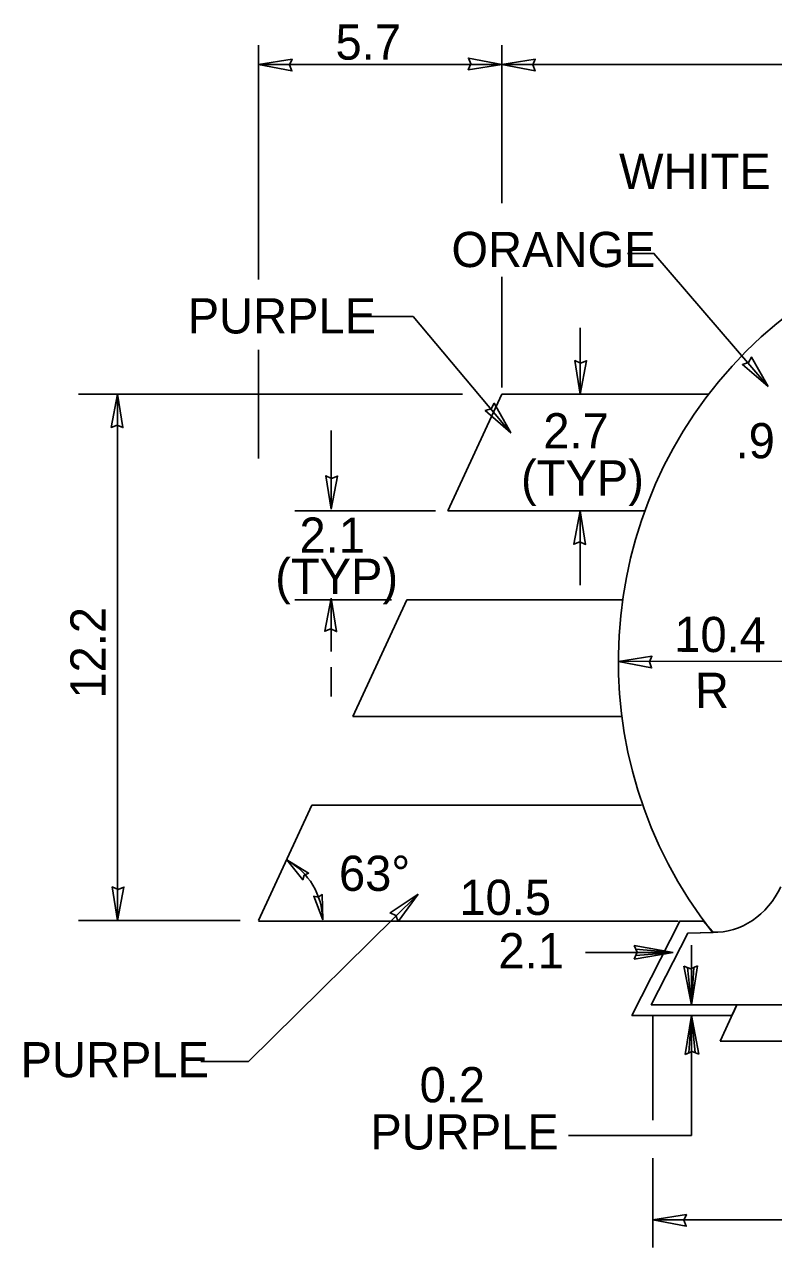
# Model space of a CAD drawing. Extents: x 10268197 to 10268826, y 2141503 to 2142677.
# Drawn here: x 10268493.92 to 10268506.08, y 2142339.57 to 2142359.44 of the extents above; entities that cross this region are included whole.
import ezdxf

# ---------------------------------------------------------------- set-up
doc = ezdxf.new("R2010")
doc.units = 0
doc.layers.add('Default', color=7, linetype='Continuous')

msp = doc.modelspace()

# ---------------------------------------------------------------- linework, layer by layer
at = {"layer": 'Default'}
for p, q in [((10268497.721, 2142355.296), (10268497.721, 2142359.103)), ((10268501.67, 2142356.534), (10268501.67, 2142359.103)), ((10268497.721, 2142358.79), (10268501.67, 2142358.79)), ((10268501.67, 2142358.79), (10268542.432, 2142358.79)), ((10268501.67, 2142353.544), (10268501.67, 2142355.338)), ((10268502.944, 2142354.509), (10268502.944, 2142353.435)), ((10268497.721, 2142352.391), (10268497.721, 2142354.155)), ((10268494.797, 2142353.435), (10268501.034, 2142353.435)), ((10268495.43, 2142353.435), (10268495.43, 2142349.147)), ((10268501.67, 2142353.435), (10268500.793, 2142351.536)), ((10268505.034, 2142353.435), (10268501.67, 2142353.435)), ((10268498.9, 2142352.844), (10268498.9, 2142351.563)), ((10268498.307, 2142351.536), (10268500.591, 2142351.536)), ((10268503.992, 2142351.536), (10268500.793, 2142351.536)), ((10268502.944, 2142351.536), (10268502.944, 2142350.329)), ((10268498.307, 2142350.095), (10268499.878, 2142350.095)), ((10268498.9, 2142350.122), (10268498.9, 2142349.251)), ((10268500.128, 2142350.095), (10268499.25, 2142348.196)), ((10268503.634, 2142350.095), (10268500.128, 2142350.095)), ((10268495.43, 2142349.147), (10268495.43, 2142344.886)), ((10268510.689, 2142349.102), (10268503.564, 2142349.091)), ((10268498.9, 2142348.997), (10268498.9, 2142348.52)), ((10268503.623, 2142348.196), (10268499.25, 2142348.196)), ((10268498.586, 2142346.756), (10268497.721, 2142344.886)), ((10268503.942, 2142346.756), (10268498.586, 2142346.756)), ((10268497.556, 2142342.591), (10268500.313, 2142345.312)), ((10268494.797, 2142344.886), (10268497.419, 2142344.886)), ((10268497.721, 2142344.874), (10268504.537, 2142344.874)), ((10268504.562, 2142344.874), (10268503.783, 2142343.341)), ((10268504.562, 2142344.874), (10268504.957, 2142344.874)), ((10268504.69, 2142344.678), (10268504.099, 2142343.516)), ((10268505.094, 2142344.69), (10268504.691, 2142344.678)), ((10268503.028, 2142344.363), (10268504.452, 2142344.363)), ((10268503.87, 2142344.368), (10268503.82, 2142344.258)), ((10268504.452, 2142344.363), (10268503.82, 2142344.258)), ((10268504.452, 2142344.363), (10268503.822, 2142344.48)), ((10268503.822, 2142344.48), (10268503.87, 2142344.368)), ((10268504.452, 2142344.363), (10268503.847, 2142344.421)), ((10268504.452, 2142344.363), (10268503.847, 2142344.316)), ((10268504.75, 2142343.516), (10268504.75, 2142344.484)), ((10268504.75, 2142343.516), (10268504.628, 2142344.144)), ((10268504.628, 2142344.144), (10268504.74, 2142344.098)), ((10268504.75, 2142343.516), (10268504.687, 2142344.12)), ((10268504.74, 2142344.098), (10268504.85, 2142344.148)), ((10268504.75, 2142343.573), (10268504.75, 2142344.193)), ((10268504.75, 2142343.516), (10268504.85, 2142344.148)), ((10268504.75, 2142343.516), (10268504.792, 2142344.121)), ((10268504.099, 2142343.516), (10268513.151, 2142343.516)), ((10268505.217, 2142342.926), (10268505.489, 2142343.516)), ((10268505.489, 2142343.516), (10268505.217, 2142342.926)), ((10268505.431, 2142343.391), (10268505.489, 2142343.516)), ((10268513.151, 2142343.516), (10268505.489, 2142343.516)), ((10268503.783, 2142343.341), (10268505.408, 2142343.341)), ((10268504.124, 2142341.641), (10268504.124, 2142343.331)), ((10268504.75, 2142343.341), (10268504.649, 2142342.708)), ((10268504.75, 2142343.341), (10268504.708, 2142342.735)), ((10268504.75, 2142341.392), (10268504.75, 2142343.341)), ((10268504.75, 2142343.341), (10268504.872, 2142342.712)), ((10268504.75, 2142343.341), (10268504.813, 2142342.736)), ((10268505.217, 2142342.926), (10268513.678, 2142342.926)), ((10268505.217, 2142342.926), (10268513.678, 2142342.926)), ((10268504.76, 2142342.758), (10268504.649, 2142342.708)), ((10268504.872, 2142342.712), (10268504.76, 2142342.758)), ((10268496.78, 2142342.591), (10268497.556, 2142342.591)), ((10268502.754, 2142341.392), (10268504.75, 2142341.392)), ((10268504.124, 2142339.572), (10268504.124, 2142341.022)), ((10268504.124, 2142340.023), (10268513.151, 2142340.023))]:
    msp.add_line(p, q, dxfattribs=at)
for points in [[(10268497.721, 2142358.79), (10268498.265, 2142358.875), (10268498.224, 2142358.782), (10268498.261, 2142358.685)], [(10268501.67, 2142358.79), (10268501.126, 2142358.704), (10268501.167, 2142358.797), (10268501.129, 2142358.894)], [(10268501.67, 2142358.79), (10268502.214, 2142358.875), (10268502.173, 2142358.782), (10268502.21, 2142358.685)], [(10268502.944, 2142353.435), (10268502.858, 2142353.979), (10268502.951, 2142353.938), (10268503.048, 2142353.975)], [(10268505.997, 2142353.56), (10268505.578, 2142353.916), (10268505.676, 2142353.946), (10268505.725, 2142354.037)], [(10268495.43, 2142353.435), (10268495.516, 2142352.891), (10268495.423, 2142352.932), (10268495.326, 2142352.894)], [(10268501.817, 2142352.807), (10268501.401, 2142353.168), (10268501.498, 2142353.196), (10268501.548, 2142353.287)], [(10268498.9, 2142351.563), (10268498.814, 2142352.107), (10268498.907, 2142352.066), (10268499.004, 2142352.103)], [(10268502.944, 2142351.536), (10268503.03, 2142350.992), (10268502.936, 2142351.033), (10268502.84, 2142350.996)], [(10268498.9, 2142350.122), (10268498.986, 2142349.578), (10268498.893, 2142349.619), (10268498.796, 2142349.582)], [(10268503.564, 2142349.091), (10268504.108, 2142349.177), (10268504.067, 2142349.084), (10268504.104, 2142348.987)], [(10268498.178, 2142345.868), (10268498.532, 2142345.654), (10268498.463, 2142345.62), (10268498.438, 2142345.547)], [(10268495.43, 2142344.886), (10268495.344, 2142345.429), (10268495.438, 2142345.389), (10268495.534, 2142345.426)], [(10268498.765, 2142344.894), (10268498.615, 2142345.278), (10268498.69, 2142345.263), (10268498.755, 2142345.306)], [(10268500.313, 2142345.312), (10268499.986, 2142344.869), (10268499.95, 2142344.964), (10268499.856, 2142345.007)], [(10268504.946, 2142344.874), (10268504.562, 2142344.874), (10268503.783, 2142343.341), (10268505.408, 2142343.341), (10268505.489, 2142343.516), (10268504.099, 2142343.516), (10268504.691, 2142344.678), (10268505.104, 2142344.69), (10268505.086, 2142344.71)], [(10268504.124, 2142340.023), (10268504.668, 2142340.108), (10268504.627, 2142340.015), (10268504.665, 2142339.918)]]:
    msp.add_lwpolyline(points, close=True, dxfattribs=at)
for points in [[(10268503.713, 2142355.719), (10268504.142, 2142355.719), (10268505.997, 2142353.56)], [(10268499.486, 2142354.694), (10268500.229, 2142354.694), (10268501.817, 2142352.807)], [(10268501.81, 2142352.808), (10268501.817, 2142352.807), (10268501.81, 2142352.812), (10268501.812, 2142352.81), (10268501.812, 2142352.81), (10268501.812, 2142352.81), (10268501.814, 2142352.808), (10268501.812, 2142352.81), (10268501.814, 2142352.808), (10268501.81, 2142352.81), (10268501.812, 2142352.808), (10268501.81, 2142352.808), (10268501.81, 2142352.808), (10268501.812, 2142352.81), (10268501.81, 2142352.812)], [(10268501.81, 2142352.808), (10268501.817, 2142352.807), (10268501.81, 2142352.812), (10268501.812, 2142352.81), (10268501.812, 2142352.81), (10268501.812, 2142352.81), (10268501.814, 2142352.808), (10268501.812, 2142352.81), (10268501.814, 2142352.808), (10268501.81, 2142352.81), (10268501.812, 2142352.808), (10268501.81, 2142352.808), (10268501.81, 2142352.808), (10268501.812, 2142352.81), (10268501.81, 2142352.812)], [(10268501.81, 2142352.808), (10268501.817, 2142352.807), (10268501.81, 2142352.812), (10268501.812, 2142352.81), (10268501.812, 2142352.81), (10268501.812, 2142352.81), (10268501.814, 2142352.808), (10268501.812, 2142352.81), (10268501.814, 2142352.808), (10268501.81, 2142352.81), (10268501.812, 2142352.808), (10268501.81, 2142352.808), (10268501.81, 2142352.808), (10268501.812, 2142352.81), (10268501.81, 2142352.812)]]:
    msp.add_lwpolyline(points, dxfattribs=at)
for centre, radius, start, end in [((10268510.689, 2142349.102), 7.125, 51.9618, 218.2529), ((10268497.63, 2142344.876), 1.132, 0.8256, 61.0937)]:
    msp.add_arc(centre, radius, start, end, dxfattribs=at)
msp.add_ellipse((10268505.116, 2142346.048), major_axis=(0, 1.356), ratio=0.897229, start_param=3.121696, end_param=4.241135, dxfattribs=at)

# ---------------------------------------------------------------- texts
for s, p in [('5.7', (10268498.97, 2142358.867)), ('WHITE', (10268503.575, 2142356.768)), ('ORANGE', (10268500.853, 2142355.498)), ('PURPLE', (10268496.569, 2142354.42)), ('2.7', (10268502.345, 2142352.553)), ('.9', (10268505.468, 2142352.392)), ('(TYP)', (10268501.983, 2142351.787)), ('2.1', (10268498.385, 2142350.858)), ('(TYP)', (10268497.99, 2142350.19)), ('63°', (10268499.026, 2142345.365)), ('10.5', (10268500.982, 2142344.975)), ('2.1', (10268501.616, 2142344.107)), ('PURPLE', (10268493.855, 2142342.337)), ('0.2', (10268500.336, 2142341.931)), ('PURPLE', (10268499.536, 2142341.165))]:
    msp.add_text(s, height=0.5717, dxfattribs=at).set_placement(p)
for s, height, rotation, p in [('12.2', 0.5717, 90, (10268495.235, 2142348.488)), ('10.4', 0.5717, 359.5763, (10268504.47, 2142349.249)), ('R', 0.572, 0.3852, (10268504.81, 2142348.335))]:
    msp.add_text(s, height=height, rotation=rotation, dxfattribs=at).set_placement(p)

doc.saveas('drawing.dxf')
